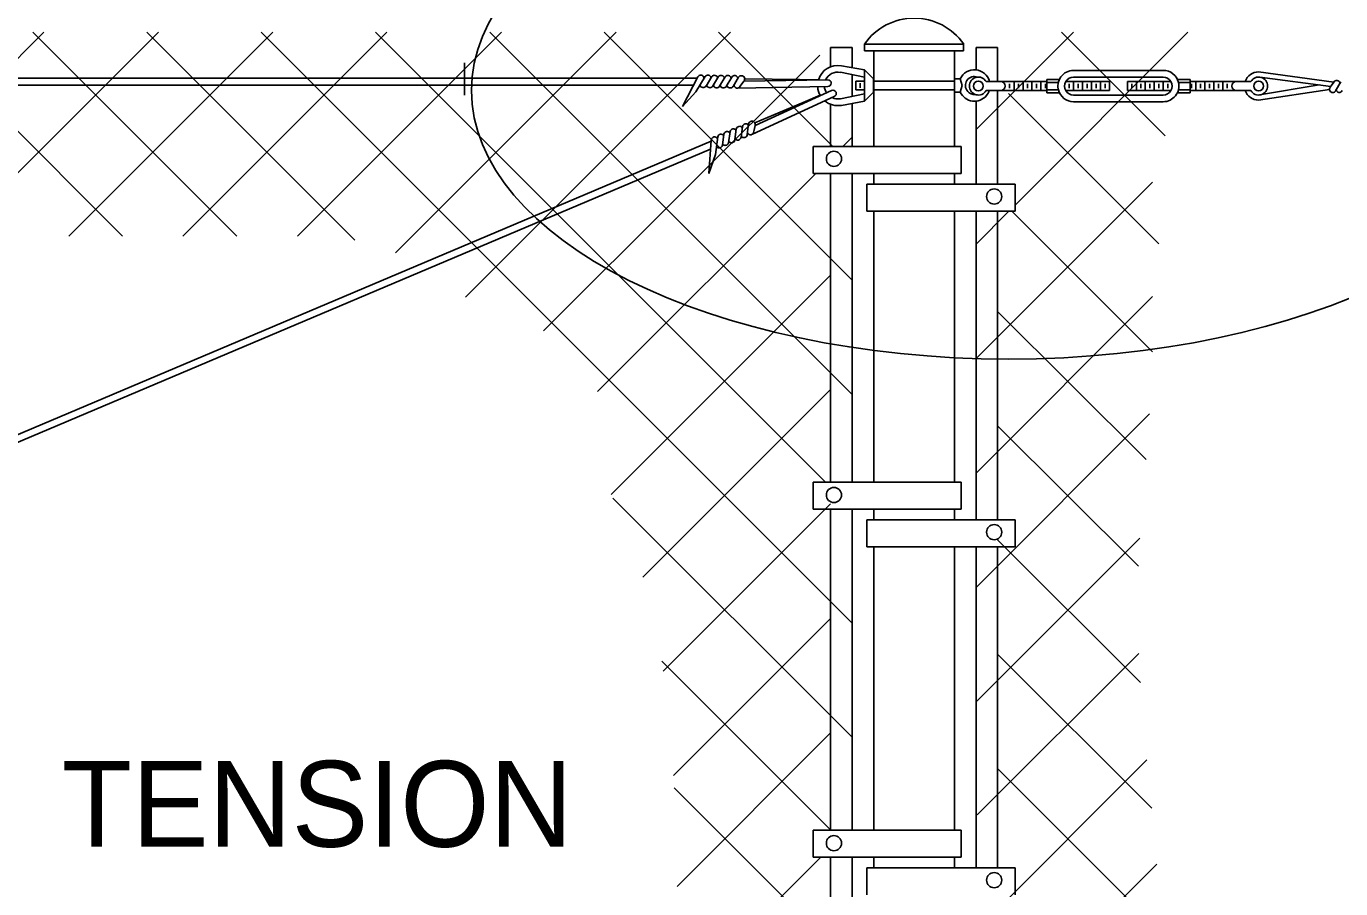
# Model space of a CAD drawing. Extents: x 99862 to 104211, y 98939 to 105076.
# Drawn here: x 101985.8 to 102230.4, y 100496.1 to 100656.6 of the extents above; entities that cross this region are included whole.
import ezdxf

# ---------------------------------------------------------------- set-up
doc = ezdxf.new("R2010")
doc.units = 0
for name, color, linetype in [('Level 11', 7, 'Continuous'), ('Level 2', 7, 'Continuous'), ('Level 20', 7, 'Continuous'), ('Level 4', 7, 'Continuous'), ('Level 7', 7, 'Continuous')]:
    doc.layers.add(name, color=color, linetype=linetype)

msp = doc.modelspace()

# ---------------------------------------------------------------- linework, layer by layer
at = {"layer": 'Level 11'}
msp.add_ellipse((102168.67, 100644.69), major_axis=(100, 0), ratio=0.5, dxfattribs=at)
at = {"layer": 'Level 2'}
for p, q in [((102110.78, 100647.23), (102107.9, 100641.72)), ((102112.13, 100647.28), (102110.41, 100644.44)), ((102113.39, 100647.29), (102112.32, 100645.53)), ((102114.65, 100647.28), (102113.51, 100645.43)), ((102115.89, 100647.25), (102114.81, 100645.48)), ((102117.12, 100647.2), (102116.07, 100645.45)), ((102118.36, 100647.17), (102117.33, 100645.45)), ((102137.31, 100648.08), (102141.81, 100647.2)), ((102137.49, 100649.31), (102141.81, 100648.54)), ((102141.81, 100648.54), (102143.5, 100646.86)), ((102141.81, 100648.54), (102141.81, 100642.7)), ((102180.72, 100648.44), (102197.38, 100648.44)), ((102180.72, 100647.19), (102197.38, 100647.19)), ((102215.15, 100648.15), (102229.14, 100646.25)), ((102215.37, 100647.17), (102228.58, 100645.45)), ((101480.47, 100647), (102110.66, 100647)), ((101481.13, 100645.7), (102109.98, 100645.7)), ((102134.99, 100645.42), (102118.25, 100645.15)), ((102119.35, 100646.41), (102118.66, 100645.47)), ((102134.98, 100646.67), (102119.35, 100646.42)), ((102129.73, 100646.75), (102119.51, 100646.89)), ((102135.66, 100644.7), (102121.45, 100638.18)), ((102133.24, 100646.7), (102129.73, 100646.75)), ((102140.16, 100646.46), (102140.16, 100644.79)), ((102140.16, 100646.46), (102141.81, 100646.46)), ((102140.16, 100644.79), (102141.81, 100644.79)), ((102141, 100646.04), (102141, 100645.21)), ((102143.48, 100646.46), (102158.63, 100646.46)), ((102143.5, 100646.46), (102143.5, 100644.79)), ((102143.5, 100645.62), (102143.5, 100644.79)), ((102143.5, 100644.79), (102158.55, 100644.79)), ((102158.55, 100646.46), (102158.55, 100644.79)), ((102159.61, 100646.87), (102160, 100645.62)), ((102159.61, 100644.37), (102160, 100645.62)), ((102167.99, 100646.35), (102164.43, 100646.35)), ((102167.99, 100644.69), (102164.43, 100644.69)), ((102175.72, 100646.35), (102167.97, 100646.35)), ((102175.72, 100644.69), (102167.97, 100644.69)), ((102168.8, 100645.94), (102168.8, 100645.1)), ((102169.63, 100646.35), (102169.63, 100644.69)), ((102170.47, 100645.94), (102170.47, 100645.1)), ((102171.3, 100646.35), (102171.3, 100644.69)), ((102172.13, 100645.94), (102172.13, 100645.1)), ((102172.96, 100646.35), (102172.96, 100644.69)), ((102173.8, 100645.94), (102173.8, 100645.1)), ((102174.63, 100646.35), (102174.63, 100644.69)), ((102175.46, 100645.94), (102175.46, 100645.1)), ((102175.72, 100646.77), (102175.72, 100644.27)), ((102178.09, 100646.77), (102175.72, 100646.77)), ((102179.29, 100646.35), (102187.39, 100646.35)), ((102179.29, 100644.69), (102187.39, 100644.69)), ((102179.89, 100645.94), (102179.89, 100645.1)), ((102180.72, 100646.35), (102180.72, 100644.69)), ((102181.56, 100645.94), (102181.56, 100645.1)), ((102182.39, 100646.35), (102182.39, 100644.69)), ((102183.22, 100645.94), (102183.22, 100645.1)), ((102184.06, 100646.35), (102184.06, 100644.69)), ((102184.89, 100645.94), (102184.89, 100645.1)), ((102185.72, 100646.35), (102185.72, 100644.69)), ((102186.56, 100645.94), (102186.56, 100645.1)), ((102187.39, 100646.35), (102187.39, 100644.69)), ((102190.72, 100646.35), (102190.72, 100644.69)), ((102198.83, 100646.35), (102190.72, 100646.35)), ((102198.83, 100644.69), (102190.72, 100644.69)), ((102191.56, 100645.94), (102191.56, 100645.1)), ((102192.39, 100646.35), (102192.39, 100644.69)), ((102193.22, 100645.94), (102193.22, 100645.1)), ((102194.05, 100646.35), (102194.05, 100644.69)), ((102194.89, 100645.94), (102194.89, 100645.1)), ((102195.72, 100646.35), (102195.72, 100644.69)), ((102196.55, 100645.94), (102196.55, 100645.1)), ((102197.39, 100646.35), (102197.39, 100644.69)), ((102198.22, 100645.94), (102198.22, 100645.1)), ((102200.02, 100646.77), (102202.38, 100646.77)), ((102202.38, 100646.77), (102202.38, 100644.27)), ((102202.38, 100646.35), (102210.15, 100646.35)), ((102202.38, 100644.69), (102210.15, 100644.69)), ((102202.65, 100645.94), (102202.65, 100645.1)), ((102203.48, 100646.35), (102203.48, 100644.69)), ((102204.31, 100645.94), (102204.31, 100645.1)), ((102205.15, 100646.35), (102205.15, 100644.69)), ((102205.98, 100645.94), (102205.98, 100645.1)), ((102206.81, 100646.35), (102206.81, 100644.69)), ((102207.65, 100645.94), (102207.65, 100645.1)), ((102208.48, 100646.35), (102208.48, 100644.69)), ((102209.31, 100645.94), (102209.31, 100645.1)), ((102210.15, 100646.35), (102213.7, 100646.35)), ((102210.15, 100644.69), (102213.7, 100644.69)), ((102215.14, 100642.9), (102228.34, 100644.85)), ((102215.34, 100643.87), (102226.44, 100645.73)), ((102228.49, 100645.32), (102229.14, 100646.25)), ((102229.46, 100644.6), (102230.42, 100646.28)), ((102110.41, 100644.44), (102107.9, 100641.72)), ((102136.16, 100643.55), (102120.95, 100636.58)), ((102130.82, 100642.65), (102121.4, 100638.67)), ((102133.55, 100643.81), (102130.82, 100642.65)), ((102137.31, 100643.17), (102141.81, 100644.06)), ((102137.49, 100641.93), (102141.81, 100642.7)), ((102141.81, 100642.7), (102143.5, 100644.39)), ((102178.09, 100644.27), (102175.72, 100644.27)), ((102180.72, 100643.85), (102197.4, 100643.85)), ((102180.72, 100642.6), (102197.4, 100642.6)), ((102200.02, 100644.27), (102202.38, 100644.27)), ((102117.94, 100637.54), (102117.67, 100635.5)), ((102119.09, 100638), (102118.83, 100635.97)), ((102120.24, 100638.47), (102119.99, 100636.48)), ((102121.45, 100638.17), (102121.2, 100637.03)), ((102113.26, 100635.24), (101796.42, 100501.1)), ((102113.27, 100635.47), (102112.86, 100629.27)), ((102114.49, 100636.07), (102114.06, 100632.78)), ((102115.64, 100636.58), (102115.37, 100634.54)), ((102116.8, 100637.08), (102116.5, 100634.93)), ((102113.16, 100633.79), (101798.09, 100500.39)), ((102114.06, 100632.78), (102112.86, 100629.27))]:
    msp.add_line(p, q, dxfattribs=at)
for points in [[(102143.5, 100646.46), (102143.5, 100646.86)], [(102143.5, 100644.79), (102143.5, 100644.39)], [(102158.55, 100646.46), (102158.55, 100646.87), (102159.61, 100646.87)], [(102158.55, 100644.79), (102158.55, 100644.37), (102159.61, 100644.37)], [(102177.89, 100646.2), (102175.72, 100646.2)], [(102177.89, 100644.84), (102175.72, 100644.84)], [(102200.22, 100646.2), (102202.38, 100646.2)], [(102200.22, 100644.84), (102202.38, 100644.84)]]:
    msp.add_lwpolyline(points, dxfattribs=at)
for centre in [(102162.99, 100645.52), (102215.15, 100645.52)]:
    msp.add_circle(centre, 0.916, dxfattribs=at)
for centre, radius, start, end in [((102111.33, 100646.94), 0.625, 5.5897, 152.4284), ((102112.63, 100646.92), 0.625, 11.8632, 144.3125), ((102113.88, 100646.9), 0.625, 11.7843, 141.8741), ((102115.13, 100646.88), 0.625, 11.904, 140.657), ((102116.38, 100646.87), 0.625, 12.036, 142.5633), ((102117.63, 100646.85), 0.625, 12.0936, 145.3228), ((102118.88, 100646.83), 0.625, 318.1467, 147.2959), ((102136.83, 100645.62), 3.75, 79.8887, 164.2198), ((102136.83, 100645.62), 2.5, 78.9793, 155.3789), ((102162.25, 100645.62), 2.92, 15.3396, 154.6231), ((102162.25, 100645.62), 1.67, 69.192, 221.9482), ((102162.99, 100645.52), 1.67, 30, 330), ((102180.72, 100645.52), 2.92, 89.9981, 197.6162), ((102180.72, 100645.52), 1.67, 89.9982, 210), ((102197.38, 100645.52), 2.92, 13.5281, 90.0019), ((102197.38, 100645.52), 1.67, 329.9987, 90.0018), ((102215.15, 100645.52), 2.63, 89.9156, 161.4419), ((102215.15, 100645.52), 1.67, 210, 150), ((102111.78, 100645.86), 0.625, 193.8848, 328.5491), ((102113.03, 100645.83), 0.625, 192.4866, 320.657), ((102114.28, 100645.81), 0.625, 191.8638, 328.6588), ((102115.54, 100645.79), 0.625, 190.9628, 331.4197), ((102116.79, 100645.78), 0.625, 192.036, 329.1632), ((102118.11, 100645.76), 0.625, 184.46, 332.4083), ((102136.83, 100645.62), 3.75, 183.5601, 210.0482), ((102136.83, 100645.62), 2.5, 184.8758, 212.7646), ((102134.99, 100646.05), 0.625, 269.1861, 89.1861), ((102135.92, 100644.13), 0.625, 292.8998, 112.8998), ((102162.25, 100645.62), 2.92, 319.9883, 341.2905), ((102167.13, 100645.52), 0.833, 270, 90), ((102180.72, 100645.52), 2.92, 193.5247, 270), ((102180.72, 100645.52), 1.67, 210, 270), ((102197.38, 100645.52), 2.92, 270, 13.5281), ((102197.38, 100645.52), 1.67, 270, 329.9987), ((102211, 100645.52), 0.833, 90, 270), ((102215.15, 100645.52), 2.63, 198.4511, 269.9156), ((102228.95, 100644.92), 0.605, 139.1935, 332.0773), ((102229.68, 100645.97), 0.605, 5.5069, 153.4551), ((102230.16, 100644.93), 0.605, 193.1404, 333.7456), ((102136.83, 100645.62), 3.75, 229.9591, 280.1113), ((102136.83, 100645.62), 2.5, 244.5384, 281.1362), ((102162.25, 100645.62), 2.92, 205.3769, 319.9883), ((102162.25, 100645.62), 1.67, 221.9482, 275.0474), ((102117.4, 100636.91), 0.625, 35.6178, 164.3707), ((102118.55, 100637.4), 0.625, 35.7497, 166.277), ((102119.7, 100637.88), 0.625, 35.8073, 169.0366), ((102120.85, 100638.37), 0.625, 341.8604, 171.0096), ((102113.9, 100635.43), 0.625, 29.3034, 176.1421), ((102115.1, 100635.94), 0.625, 35.5769, 168.0263), ((102115.9, 100635.1), 0.625, 216.2003, 344.3707), ((102116.25, 100636.42), 0.625, 35.4981, 165.5878), ((102117.05, 100635.58), 0.625, 215.5775, 352.3726), ((102118.21, 100636.08), 0.625, 214.6765, 355.1334), ((102119.37, 100636.56), 0.625, 215.7497, 352.8769), ((102120.58, 100637.07), 0.625, 208.1738, 356.122), ((102114.74, 100634.62), 0.625, 217.5985, 352.2628)]:
    msp.add_arc(centre, radius, start, end, dxfattribs=at)
at = {"layer": 'Level 4'}
for p, q in [((101951.13, 100617.58), (101989.08, 100655.53)), ((102003.69, 100617.58), (101965.74, 100655.53)), ((101972.43, 100617.58), (102010.39, 100655.53)), ((102024.96, 100617.58), (101987.01, 100655.53)), ((101993.71, 100617.58), (102031.67, 100655.53)), ((102046.93, 100616.85), (102008.27, 100655.53)), ((102014.97, 100617.58), (102052.92, 100655.53)), ((102139.49, 100545.55), (102029.52, 100655.53)), ((102036.3, 100617.58), (102074.26, 100655.53)), ((102134.54, 100571.78), (102050.79, 100655.53)), ((102054.51, 100614.46), (102095.58, 100655.53)), ((102067.56, 100606.21), (102116.89, 100655.53)), ((102139.49, 100588.11), (102072.07, 100655.53)), ((102139.49, 100609.39), (102093.36, 100655.53)), ((102135.89, 100634.26), (102114.63, 100655.53)), ((102162.56, 100637.41), (102180.68, 100655.53)), ((102169.84, 100623.37), (102202, 100655.53)), ((102197.76, 100636.25), (102178.48, 100655.53)), ((102067.36, 100643.8), (102067.36, 100649.82)), ((102082.09, 100599.92), (102133.47, 100651.29)), ((102196.56, 100616.16), (102168.58, 100644.15)), ((102137.75, 100634.26), (102139.49, 100636)), ((102092.13, 100588.65), (102132.74, 100629.25)), ((102162.56, 100594.8), (102195.41, 100627.64)), ((102162.56, 100616.1), (102168.69, 100622.23)), ((102195.39, 100596.05), (102169.21, 100622.23)), ((102094.64, 100569.5), (102135.47, 100610.32)), ((102162.56, 100573.47), (102195.41, 100606.32)), ((102194.19, 100575.97), (102166.58, 100603.57)), ((102100.54, 100554.09), (102135.47, 100589.02)), ((102162.56, 100552.18), (102194.86, 100584.47)), ((102192.76, 100556.11), (102166.58, 100582.29)), ((102139.49, 100524.27), (102094.96, 100568.81)), ((102104.35, 100536.6), (102135.47, 100567.71)), ((102162.56, 100530.87), (102193.04, 100561.35)), ((102193.15, 100534.45), (102166.58, 100561.02)), ((102106.25, 100517.15), (102135.47, 100546.38)), ((102162.78, 100509.82), (102192.84, 100539.87)), ((102195.27, 100511.05), (102166.58, 100539.74)), ((102135.51, 100507), (102104.07, 100538.45)), ((102106.91, 100496.52), (102135.47, 100525.09)), ((102162.56, 100488.28), (102194.37, 100520.08)), ((102196.98, 100488.06), (102166.58, 100518.46)), ((102139.49, 100481.77), (102106.38, 100514.88)), ((102106.55, 100474.86), (102133.68, 100501.98)), ((102162.56, 100467.04), (102196.21, 100500.68))]:
    msp.add_line(p, q, dxfattribs=at)
at = {"layer": 'Level 7'}
for p, q in [((102135.47, 100652.7), (102139.49, 100652.7)), ((102135.47, 100649.12), (102135.47, 100652.7)), ((102139.49, 100648.96), (102139.49, 100652.7)), ((102141.8, 100653.32), (102160.25, 100653.32)), ((102141.8, 100652.07), (102141.8, 100653.32)), ((102160.25, 100652.07), (102141.8, 100652.07)), ((102143.51, 100634.26), (102143.51, 100652.07)), ((102158.55, 100634.26), (102158.55, 100652.07)), ((102160.25, 100652.07), (102160.25, 100653.32)), ((102162.56, 100648.52), (102162.56, 100652.7)), ((102166.58, 100652.7), (102162.56, 100652.7)), ((102166.58, 100646.35), (102166.58, 100652.7)), ((102139.49, 100644.71), (102139.49, 100647.65)), ((102139.49, 100643.6), (102139.49, 100644.71)), ((102166.58, 100643.42), (102166.58, 100644.69)), ((102139.49, 100634.26), (102139.49, 100642.29)), ((102162.56, 100627.25), (102162.56, 100642.72)), ((102166.58, 100627.25), (102166.58, 100643.42)), ((102135.47, 100634.26), (102135.47, 100641.94)), ((102132.22, 100634.26), (102159.81, 100634.26)), ((102132.22, 100629.25), (102132.22, 100634.26)), ((102159.81, 100629.25), (102159.81, 100634.26)), ((102132.22, 100629.25), (102159.81, 100629.25)), ((102135.47, 100571.78), (102135.47, 100629.25)), ((102139.49, 100571.78), (102139.49, 100629.25)), ((102143.51, 100627.25), (102143.51, 100629.25)), ((102158.55, 100627.25), (102158.55, 100629.25)), ((102169.84, 100627.25), (102142.25, 100627.25)), ((102142.25, 100622.23), (102142.25, 100627.25)), ((102169.84, 100622.23), (102169.84, 100627.25)), ((102169.84, 100622.23), (102142.25, 100622.23)), ((102143.51, 100571.78), (102143.51, 100622.23)), ((102158.55, 100571.78), (102158.55, 100622.23)), ((102162.56, 100564.76), (102162.56, 100622.23)), ((102166.58, 100564.76), (102166.58, 100622.23)), ((102132.22, 100571.78), (102159.81, 100571.78)), ((102132.22, 100566.76), (102132.22, 100571.78)), ((102159.81, 100571.78), (102159.81, 100566.76)), ((102132.22, 100566.76), (102159.81, 100566.76)), ((102135.47, 100507), (102135.47, 100566.76)), ((102139.49, 100507), (102139.49, 100566.76)), ((102143.51, 100564.74), (102143.51, 100566.75)), ((102158.55, 100564.74), (102158.55, 100566.75)), ((102142.25, 100559.75), (102142.25, 100564.76)), ((102169.84, 100564.76), (102142.25, 100564.76)), ((102169.84, 100559.75), (102169.84, 100564.76)), ((102169.84, 100559.75), (102142.25, 100559.75)), ((102143.51, 100507), (102143.51, 100559.75)), ((102158.55, 100507), (102158.55, 100559.75)), ((102162.56, 100499.98), (102162.56, 100559.75)), ((102166.58, 100499.98), (102166.58, 100559.75)), ((102132.22, 100507), (102159.81, 100507)), ((102132.22, 100501.98), (102132.22, 100507)), ((102159.81, 100507), (102159.81, 100501.98)), ((102132.22, 100501.98), (102159.81, 100501.98)), ((102135.47, 100443.78), (102135.47, 100501.98)), ((102139.49, 100443.78), (102139.49, 100501.98)), ((102143.51, 100499.97), (102143.51, 100501.97)), ((102158.55, 100499.97), (102158.55, 100501.97)), ((102169.84, 100499.98), (102142.25, 100499.98)), ((102142.25, 100494.97), (102142.25, 100499.98)), ((102169.84, 100494.97), (102169.84, 100499.98))]:
    msp.add_line(p, q, dxfattribs=at)
for centre in [(102136.11, 100631.97), (102165.94, 100624.95), (102136.11, 100569.38), (102165.94, 100562.46), (102136.11, 100504.56), (102165.94, 100497.68)]:
    msp.add_circle(centre, 1.41, dxfattribs=at)
msp.add_arc((102151.03, 100646.98), 11.2, 34.5285, 145.4715, dxfattribs=at)

# ---------------------------------------------------------------- texts
at = {"layer": 'Level 20'}
msp.add_text('TENSION', height=16, rotation=360, dxfattribs=at).set_placement((101992.39, 100503.88))

doc.saveas('drawing.dxf')
